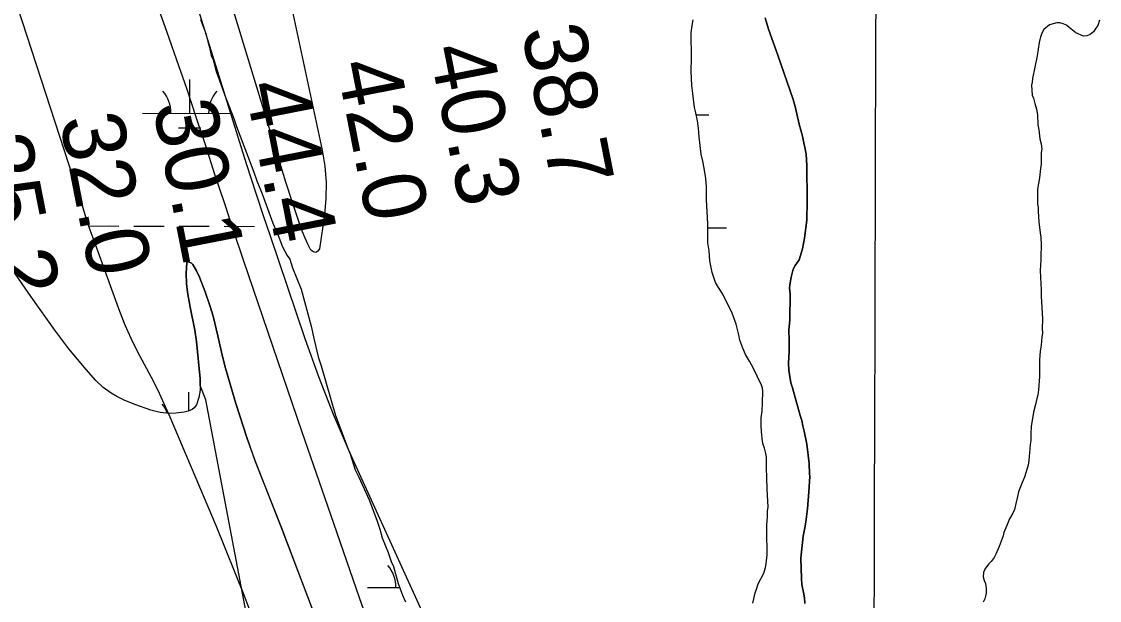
# Model space of a CAD drawing. Extents: x 3161665 to 3199565, y 885729 to 911164.
# Drawn here: x 3180653 to 3181798, y 893161 to 893776 of the extents above; entities that cross this region are included whole.
import ezdxf

# ---------------------------------------------------------------- set-up
doc = ezdxf.new("R2010")
doc.units = 0
for name, color, linetype in [('V-GRID-MAJR', 7, 'Continuous'), ('V-RIVR-RANG', 7, 'Continuous'), ('V-SITE-VEGE', 7, 'Continuous'), ('V-TOPO-MAJR', 7, 'Continuous'), ('V-TOPO-MINR', 7, 'Continuous'), ('V-TOPO-SHOR', 7, 'Continuous'), ('V-WETL-SWMP', 7, 'Continuous')]:
    doc.layers.add(name, color=color, linetype=linetype)

msp = doc.modelspace()

# ---------------------------------------------------------------- linework, layer by layer
at = {"layer": 'V-GRID-MAJR'}
msp.add_spline([(3181553.2, 891152.2), (3181570, 897211.5), (3181586.7, 903274.3), (3181603.5, 909337.1), (3181603.5, 909340.5)], degree=3, dxfattribs=at)
at = {"layer": 'V-SITE-VEGE'}
for p, q in [((3181446.6, 893767.9), (3181443.1, 893779.9)), ((3181745.1, 893772.6), (3181739.1, 893767.8)), ((3181752.9, 893774.6), (3181745.1, 893772.6)), ((3181756.2, 893774.6), (3181752.9, 893774.6)), ((3181759.8, 893773.7), (3181756.2, 893774.6)), ((3181763.4, 893772.1), (3181759.8, 893773.7)), ((3181766.1, 893769.7), (3181763.4, 893772.1)), ((3181769.7, 893767), (3181766.1, 893769.7)), ((3181794.3, 893769.2), (3181791.9, 893765.3)), ((3181796.4, 893771.9), (3181794.3, 893769.2)), ((3181798.3, 893777.6), (3181796.4, 893771.9)), ((3181456.6, 893740.2), (3181446.6, 893767.9)), ((3181735.7, 893759.7), (3181734.2, 893753.8)), ((3181737.3, 893764.5), (3181735.7, 893759.7)), ((3181739.1, 893767.8), (3181737.3, 893764.5)), ((3181773.3, 893764), (3181769.7, 893767)), ((3181781.3, 893760.6), (3181773.3, 893764)), ((3181784.9, 893760.9), (3181781.3, 893760.6)), ((3181788.5, 893762.3), (3181784.9, 893760.9)), ((3181791.9, 893765.3), (3181788.5, 893762.3)), ((3181734.2, 893753.8), (3181732, 893739.7)), ((3181472.7, 893693.3), (3181456.6, 893740.2)), ((3181732, 893739.7), (3181727, 893715.7)), ((3181727, 893715.7), (3181726.7, 893711.8)), ((3181726.7, 893711.8), (3181726, 893708.5)), ((3181726, 893708.5), (3181726.9, 893697.7)), ((3181474.8, 893685.8), (3181472.7, 893693.3)), ((3181726.9, 893697.7), (3181728, 893694.7)), ((3181728, 893694.7), (3181729.5, 893689)), ((3181729.5, 893689), (3181731.5, 893683)), ((3181479.1, 893666.9), (3181474.8, 893685.8)), ((3181731.5, 893683), (3181732.4, 893677)), ((3181482.6, 893654.2), (3181479.1, 893666.9)), ((3181732.4, 893677), (3181732.9, 893666.2)), ((3181732.9, 893666.2), (3181733.8, 893661.1)), ((3181733.8, 893661.1), (3181734.9, 893651.4)), ((3181486.4, 893635), (3181482.6, 893654.2)), ((3181734.9, 893651.4), (3181736.4, 893646)), ((3181736.4, 893646), (3181736.9, 893640.3)), ((3181487.2, 893623), (3181486.4, 893635)), ((3181736.3, 893636.7), (3181736.2, 893624.4)), ((3181736.9, 893640.3), (3181736.3, 893636.7)), ((3181487.5, 893585.5), (3181487.2, 893623)), ((3181736.2, 893624.4), (3181735.6, 893619.9)), ((3181734.6, 893609.8), (3181732.4, 893597.8)), ((3181735.6, 893619.9), (3181734.6, 893609.8)), ((3181732.4, 893597.8), (3181732.3, 893581.9)), ((3181487.4, 893565.1), (3181487.5, 893585.5)), ((3181732.3, 893581.9), (3181733.2, 893578.3)), ((3181733.2, 893578.3), (3181733.1, 893574.1)), ((3181484.8, 893545.9), (3181487.4, 893565.1)), ((3181733.1, 893574.1), (3181733.7, 893563.3)), ((3181733.7, 893563.3), (3181735.1, 893551.5)), ((3181735.1, 893551.5), (3181735.9, 893546.7)), ((3181482.6, 893534.5), (3181484.8, 893545.9)), ((3181735.9, 893546.7), (3181736.2, 893538.6)), ((3181479, 893522.9), (3181482.6, 893534.5)), ((3181736.2, 893538.6), (3181735.8, 893526)), ((3180827.4, 893508.1), (3180828.1, 893520)), ((3180828.1, 893520), (3180828.8, 893520.8)), ((3180828.8, 893520.8), (3180830.1, 893520.8)), ((3180830.1, 893520.8), (3180833.3, 893519.2)), ((3180833.3, 893519.2), (3180834.8, 893517.7)), ((3180834.8, 893517.7), (3180838.7, 893511.1)), ((3181474.7, 893516.9), (3181477.4, 893520.2)), ((3181477.4, 893520.2), (3181479, 893522.9)), ((3181736.1, 893522.7), (3181735.4, 893511.3)), ((3181735.8, 893526), (3181736.1, 893522.7)), ((3180827.9, 893497.7), (3180827.4, 893508.1)), ((3180838.7, 893511.1), (3180841.9, 893504.2)), ((3181470.7, 893504.3), (3181472.6, 893512.7)), ((3181472.6, 893512.7), (3181474.7, 893516.9)), ((3181735.4, 893511.3), (3181735.9, 893497.2)), ((3180829, 893488.5), (3180827.9, 893497.7)), ((3180841.9, 893504.2), (3180847.7, 893488.7)), ((3181468.8, 893492.6), (3181469.2, 893496.2)), ((3181469.2, 893496.2), (3181470.7, 893504.3)), ((3181735.9, 893497.2), (3181736.4, 893490.9)), ((3180831.9, 893472.4), (3180829, 893488.5)), ((3180847.7, 893488.7), (3180853.1, 893473.3)), ((3181469.4, 893486.3), (3181468.8, 893492.6)), ((3181469.2, 893459), (3181469.4, 893486.3)), ((3181736.4, 893490.9), (3181736.4, 893484)), ((3181736.4, 893484), (3181737.7, 893459.7)), ((3180836.8, 893448.1), (3180831.9, 893472.4)), ((3180853.1, 893473.3), (3180856.2, 893462.8)), ((3180856.2, 893462.8), (3180861.2, 893442.1)), ((3181468.2, 893447.9), (3181469.2, 893459)), ((3181737.7, 893459.7), (3181737.3, 893449.8)), ((3181737.3, 893449.8), (3181737.6, 893445.3)), ((3180838.7, 893436), (3180836.8, 893448.1)), ((3180861.2, 893442.1), (3180865.9, 893421.4)), ((3181468.4, 893437.4), (3181468.2, 893447.9)), ((3181468.3, 893425.7), (3181468.4, 893437.4)), ((3181736.9, 893440.5), (3181736.3, 893432.1)), ((3181737.6, 893445.3), (3181736.9, 893440.5)), ((3180842.4, 893396.2), (3180838.7, 893436)), ((3181467.9, 893412.5), (3181468.3, 893425.7)), ((3181735.3, 893425.5), (3181734.7, 893416.6)), ((3181736.3, 893432.1), (3181735.3, 893425.5)), ((3180865.9, 893421.4), (3180869.5, 893407.7)), ((3181734.7, 893416.6), (3181734.5, 893398.6)), ((3180869.5, 893407.7), (3180880.4, 893370.1)), ((3181468.2, 893405.6), (3181467.9, 893412.5)), ((3181468.7, 893400.8), (3181468.2, 893405.6)), ((3180842.6, 893389.3), (3180842.4, 893396.2)), ((3181470.2, 893392.1), (3181468.7, 893400.8)), ((3181471.9, 893386.7), (3181470.2, 893392.1)), ((3181734.5, 893398.6), (3181733.5, 893384.5)), ((3180848.3, 893374.1), (3180842.6, 893389.3)), ((3181480.1, 893357.3), (3181471.9, 893386.7)), ((3181733.5, 893384.5), (3181732.6, 893378.8)), ((3180898.3, 893112.3), (3180848.3, 893374.1)), ((3180880.4, 893370.1), (3180892.3, 893332.8)), ((3181730.4, 893368.9), (3181728.2, 893360.8)), ((3181731.6, 893375.2), (3181730.4, 893368.9)), ((3181732.6, 893378.8), (3181731.6, 893375.2)), ((3181481.9, 893352.1), (3181480.1, 893357.3)), ((3181728.2, 893360.8), (3181725.7, 893345.5)), ((3181483, 893346.4), (3181481.9, 893352.1)), ((3181484.5, 893340.7), (3181483, 893346.4)), ((3181725.7, 893345.5), (3181725.4, 893337.7)), ((3181487.4, 893326.9), (3181484.5, 893340.7)), ((3181725.4, 893337.7), (3181725.3, 893330.8)), ((3180892.3, 893332.8), (3180901, 893308.3)), ((3181489.6, 893306.2), (3181487.4, 893326.9)), ((3181724.7, 893326.6), (3181723.1, 893309.5)), ((3181725.3, 893330.8), (3181724.7, 893326.6)), ((3180901, 893308.3), (3180928.8, 893237.8)), ((3181490.2, 893295.4), (3181489.6, 893306.2)), ((3181722.4, 893304.4), (3181718.7, 893291.6)), ((3181723.1, 893309.5), (3181722.4, 893304.4)), ((3181489.4, 893276.2), (3181490.4, 893292.4)), ((3181490.4, 893292.4), (3181490.2, 893295.4)), ((3181718.7, 893291.6), (3181716, 893285.9)), ((3181714.4, 893281.4), (3181712.3, 893276)), ((3181716, 893285.9), (3181714.4, 893281.4)), ((3181487.8, 893257.9), (3181489.4, 893276.2)), ((3181709.8, 893265.2), (3181708, 893257.5)), ((3181711.1, 893271.2), (3181709.8, 893265.2)), ((3181712.3, 893276), (3181711.1, 893271.2)), ((3181486.5, 893246.8), (3181487.8, 893257.9)), ((3181708, 893257.5), (3181706.1, 893253.3)), ((3181485.5, 893239.6), (3181486.5, 893246.8)), ((3181702.8, 893247.3), (3181700, 893240.4)), ((3181706.1, 893253.3), (3181702.8, 893247.3)), ((3180928.8, 893237.8), (3180972.7, 893122.6)), ((3181483.4, 893229.1), (3181485.5, 893239.6)), ((3181696.7, 893232.9), (3181695.8, 893229.3)), ((3181700, 893240.4), (3181696.7, 893232.9)), ((3181480.8, 893205.5), (3181483.4, 893229.1)), ((3181695.8, 893229.3), (3181691.5, 893218)), ((3181688.1, 893209.9), (3181686.3, 893206.3)), ((3181691.5, 893218), (3181688.1, 893209.9)), ((3181481.5, 893184.1), (3181480.8, 893205.5)), ((3181680.5, 893199.2), (3181676.6, 893193.8)), ((3181683.3, 893202.1), (3181680.5, 893199.2)), ((3181686.3, 893206.3), (3181683.3, 893202.1)), ((3181675.1, 893190.2), (3181674.7, 893185.7)), ((3181674.7, 893185.7), (3181675.6, 893181.8)), ((3181676.6, 893193.8), (3181675.1, 893190.2)), ((3181482.1, 893177.5), (3181481.5, 893184.1)), ((3181484.1, 893167.3), (3181482.1, 893177.5)), ((3181675.6, 893181.8), (3181677.1, 893178.8)), ((3181677.1, 893178.8), (3181677.9, 893173.7)), ((3181677.9, 893173.7), (3181677.9, 893168.3)), ((3181484.7, 893163.4), (3181484.1, 893167.3)), ((3181485.2, 893157.4), (3181484.7, 893163.4)), ((3181676.4, 893162.3), (3181674.5, 893158.7)), ((3181677.3, 893165.3), (3181676.4, 893162.3)), ((3181677.9, 893168.3), (3181677.3, 893165.3))]:
    msp.add_line(p, q, dxfattribs=at)
at = {"layer": 'V-TOPO-MAJR'}
msp.add_lwpolyline([(3181343.1, 892486.4), (3181319.1, 892555.9), (3181294.9, 892625.4), (3181270.7, 892694.8), (3181241.9, 892777.2), (3181232, 892805.4), (3181221.9, 892833.5), (3181001.3, 893318.7), (3180984.3, 893358.2), (3180968.7, 893398.2), (3180954.2, 893438.7), (3180916.7, 893549), (3180909.8, 893569.5), (3180903, 893590.1), (3180896.3, 893610.7), (3180889.7, 893631.4), (3180849, 893761.2), (3180822.7, 893847)], dxfattribs=at)
at = {"layer": 'V-TOPO-MINR'}
for points in [[(3180889.3, 894026.8), (3180972.2, 893639.4), (3180974.9, 893622.3), (3180976.4, 893605.1), (3180976.1, 893588), (3180974.5, 893570.7), (3180969.3, 893534.6), (3180967.4, 893531.9), (3180965.4, 893530.6), (3180962.9, 893531.1), (3180960.2, 893533), (3180956.9, 893539.4), (3180953.9, 893545.9), (3180951.1, 893552.6), (3180948.7, 893559.4), (3180939.1, 893587.8), (3180937.6, 893592.3), (3180936.2, 893596.7), (3180934.8, 893601.1), (3180933.4, 893605.5), (3180780.7, 894106.2)], [(3181395.1, 892231.3), (3181147.5, 892778.3), (3181135.9, 892811.7), (3181124.1, 892845.2), (3181112.3, 892878.6), (3181073.7, 892987.5), (3181042.6, 893075.5), (3181011.8, 893163.5), (3180981.3, 893251.6), (3180951, 893339.7), (3180888.6, 893522.5), (3180878.3, 893552.8), (3180868.2, 893583.2), (3180858.2, 893613.6), (3180848.3, 893644.1), (3180838.3, 893674.5), (3180828.2, 893704.9), (3180817.7, 893735.2), (3180807.1, 893765.4), (3180759.8, 893897.1)], [(3180623.3, 893867.9), (3180717.6, 893578), (3180721.4, 893566.4), (3180725.3, 893554.8), (3180729.4, 893543.3), (3180733.5, 893531.8), (3180756.8, 893468.3), (3180762.5, 893453.8), (3180768.6, 893439.5), (3180775.5, 893425.6), (3180782.8, 893411.8), (3180790.2, 893398.1), (3180797.3, 893384.2), (3180803.9, 893370.1), (3180810.3, 893355.9), (3180859.5, 893239.6), (3180888.9, 893166.5), (3180916.4, 893092.9)]]:
    msp.add_lwpolyline(points, dxfattribs=at)
at = {"layer": 'V-TOPO-SHOR'}
for points in [[(3181443.1, 893779.9), (3181446.6, 893767.9), (3181456.6, 893740.2), (3181472.7, 893693.3), (3181474.8, 893685.8), (3181479.1, 893666.9), (3181482.6, 893654.2), (3181486.4, 893635), (3181487.2, 893623), (3181487.5, 893585.5), (3181487.4, 893565.1), (3181484.8, 893545.9), (3181482.6, 893534.5), (3181479, 893522.9), (3181477.4, 893520.2), (3181474.7, 893516.9), (3181472.6, 893512.7), (3181470.7, 893504.3), (3181469.2, 893496.2), (3181468.8, 893492.6), (3181469.4, 893486.3), (3181469.2, 893459), (3181468.2, 893447.9), (3181468.4, 893437.4), (3181468.3, 893425.7), (3181467.9, 893412.5), (3181468.2, 893405.6), (3181468.7, 893400.8), (3181470.2, 893392.1), (3181471.9, 893386.7), (3181480.1, 893357.3), (3181481.9, 893352.1), (3181483, 893346.4), (3181484.5, 893340.7), (3181487.4, 893326.9), (3181489.6, 893306.2), (3181490.2, 893295.4), (3181490.4, 893292.4), (3181489.4, 893276.2), (3181487.8, 893257.9), (3181486.5, 893246.8), (3181485.5, 893239.6), (3181483.4, 893229.1), (3181480.8, 893205.5), (3181481.5, 893184.1), (3181482.1, 893177.5), (3181484.1, 893167.3), (3181484.7, 893163.4), (3181485.2, 893157.4)], [(3181798.3, 893777.6), (3181796.4, 893771.9), (3181794.3, 893769.2), (3181791.9, 893765.3), (3181788.5, 893762.3), (3181784.9, 893760.9), (3181781.3, 893760.6), (3181773.3, 893764), (3181769.7, 893767), (3181766.1, 893769.7), (3181763.4, 893772.1), (3181759.8, 893773.7), (3181756.2, 893774.6), (3181752.9, 893774.6), (3181745.1, 893772.6), (3181739.1, 893767.8), (3181737.3, 893764.5), (3181735.7, 893759.7), (3181734.2, 893753.8), (3181732, 893739.7), (3181727, 893715.7), (3181726.7, 893711.8), (3181726, 893708.5), (3181726.9, 893697.7), (3181728, 893694.7), (3181729.5, 893689), (3181731.5, 893683), (3181732.4, 893677), (3181732.9, 893666.2), (3181733.8, 893661.1), (3181734.9, 893651.4), (3181736.4, 893646), (3181736.9, 893640.3), (3181736.3, 893636.7), (3181736.2, 893624.4), (3181735.6, 893619.9), (3181734.6, 893609.8), (3181732.4, 893597.8), (3181732.3, 893581.9), (3181733.2, 893578.3), (3181733.1, 893574.1), (3181733.7, 893563.3), (3181735.1, 893551.5), (3181735.9, 893546.7), (3181736.2, 893538.6), (3181735.8, 893526), (3181736.1, 893522.7), (3181735.4, 893511.3), (3181735.9, 893497.2), (3181736.4, 893490.9), (3181736.4, 893484), (3181737.7, 893459.7), (3181737.3, 893449.8), (3181737.6, 893445.3), (3181736.9, 893440.5), (3181736.3, 893432.1), (3181735.3, 893425.5), (3181734.7, 893416.6), (3181734.5, 893398.6), (3181733.5, 893384.5), (3181732.6, 893378.8), (3181731.6, 893375.2), (3181730.4, 893368.9), (3181728.2, 893360.8)], [(3181728.2, 893360.8), (3181725.7, 893345.5), (3181725.4, 893337.7), (3181725.3, 893330.8), (3181724.7, 893326.6), (3181723.1, 893309.5), (3181722.4, 893304.4), (3181718.7, 893291.6), (3181716, 893285.9), (3181714.4, 893281.4), (3181712.3, 893276), (3181711.1, 893271.2), (3181709.8, 893265.2), (3181708, 893257.5), (3181706.1, 893253.3), (3181702.8, 893247.3), (3181700, 893240.4), (3181696.7, 893232.9), (3181695.8, 893229.3), (3181691.5, 893218), (3181688.1, 893209.9), (3181686.3, 893206.3), (3181683.3, 893202.1), (3181680.5, 893199.2), (3181676.6, 893193.8), (3181675.1, 893190.2), (3181674.7, 893185.7), (3181675.6, 893181.8), (3181677.1, 893178.8), (3181677.9, 893173.7), (3181677.9, 893168.3), (3181677.3, 893165.3), (3181676.4, 893162.3), (3181674.5, 893158.7)]]:
    msp.add_lwpolyline(points, dxfattribs=at)
at = {"layer": 'V-WETL-SWMP'}
for p, q in [((3180831.3, 893678.5), (3180831.4, 893714.5)), ((3180781.3, 893678.7), (3180876.3, 893678.4)), ((3181369.5, 893677), (3181383.2, 893677)), ((3180819.3, 893663.1), (3180843.3, 893663.1)), ((3180724.1, 893558.8), (3180756.1, 893558.7)), ((3180772.1, 893558.6), (3180804.1, 893558.5)), ((3180820.1, 893558.5), (3180852.1, 893558.4)), ((3180868.1, 893558.4), (3180900.1, 893558.3)), ((3181382, 893556.9), (3181402, 893556.9)), ((3180830.4, 893362.3), (3180830.5, 893381.9)), ((3181020.4, 893174.5), (3181054.4, 893174.4))]:
    msp.add_line(p, q, dxfattribs=at)
for points in [[(3180842.9, 893778.3), (3180848.6, 893763.3), (3180850.5, 893754.9), (3180852.4, 893748.4), (3180854.3, 893740), (3180856.2, 893735.4), (3180859.4, 893723.1), (3180861.3, 893718.5), (3180868.2, 893698.4), (3180878.4, 893673), (3180880.9, 893664.6), (3180899.4, 893615.8), (3180902.6, 893606.7), (3180908.3, 893593.1), (3180919.7, 893561.9), (3180924.2, 893551.5), (3180929.9, 893536.5), (3180935, 893527.4), (3180937.6, 893523.5), (3180940.7, 893514.4), (3180949.7, 893491.7), (3180960.4, 893452.1), (3180963.5, 893437.8), (3180967.9, 893419.6), (3180971.1, 893409.9), (3180986.2, 893357.2), (3180999.6, 893321.5), (3181001.5, 893317.6)], [(3181430, 893157.8), (3181431, 893162.3), (3181432.5, 893168.6), (3181433.7, 893172.5), (3181435.6, 893178.2), (3181441.4, 893189.8), (3181443.2, 893195.5), (3181444.1, 893199.4), (3181445.1, 893209.3), (3181444.7, 893234.8), (3181444.7, 893240.8), (3181445.4, 893249.8), (3181445.5, 893255.5), (3181446.1, 893260), (3181445.6, 893272.3), (3181445, 893278.9), (3181444.8, 893291.5), (3181444.3, 893301.1), (3181444.4, 893312.8), (3181443.8, 893316.7), (3181442.4, 893322.4), (3181440.9, 893326.4), (3181440.3, 893330), (3181439.2, 893339.9), (3181438.6, 893346.5), (3181438.7, 893354.9), (3181439.7, 893361.8), (3181440.3, 893370.5), (3181440.4, 893383.1), (3181440.1, 893386.4), (3181438.7, 893390.6), (3181436.3, 893395.1), (3181432.8, 893402.9), (3181428.6, 893411.3), (3181426.2, 893415), (3181422.1, 893422.2), (3181419.2, 893428.8), (3181416.2, 893437.5), (3181414.8, 893442.9), (3181412.1, 893454.4), (3181408, 893466.1), (3181401.2, 893479.9), (3181397.1, 893487.5), (3181393.5, 893493.5), (3181390.3, 893498.6), (3181386.8, 893509.2), (3181384.1, 893521.8), (3181383.3, 893532.3), (3181381.9, 893541), (3181382, 893561.1), (3181380.7, 893586.9), (3181380.5, 893600.4), (3181380, 893609.1), (3181378.3, 893620.2), (3181376.8, 893627.7), (3181375.1, 893635.2), (3181372.8, 893653.6), (3181372, 893662.6), (3181370.9, 893670.7), (3181369.1, 893679.1), (3181367.7, 893684.8), (3181366, 893699.5), (3181365.1, 893708.2), (3181364.4, 893722.9), (3181364.5, 893737), (3181364.4, 893764), (3181365.3, 893771.8), (3181366.3, 893777.8)], [(3181443.1, 893779.9), (3181446.6, 893767.9), (3181456.6, 893740.2), (3181472.7, 893693.3), (3181474.8, 893685.8), (3181479.1, 893666.9), (3181482.6, 893654.2), (3181486.4, 893635), (3181487.2, 893623), (3181487.5, 893585.5), (3181487.4, 893565.1), (3181484.8, 893545.9), (3181482.6, 893534.5), (3181479, 893522.9), (3181477.4, 893520.2), (3181474.7, 893516.9), (3181472.6, 893512.7), (3181470.7, 893504.3), (3181469.2, 893496.2), (3181468.8, 893492.6), (3181469.4, 893486.3), (3181469.2, 893459), (3181468.2, 893447.9), (3181468.4, 893437.4), (3181468.3, 893425.7), (3181467.9, 893412.5), (3181468.2, 893405.6), (3181468.7, 893400.8), (3181470.2, 893392.1), (3181471.9, 893386.7), (3181480.1, 893357.3), (3181481.9, 893352.1), (3181483, 893346.4), (3181484.5, 893340.7), (3181487.4, 893326.9), (3181489.6, 893306.2), (3181490.2, 893295.4), (3181490.4, 893292.4), (3181489.4, 893276.2), (3181487.8, 893257.9), (3181486.5, 893246.8), (3181485.5, 893239.6), (3181483.4, 893229.1), (3181480.8, 893205.5), (3181481.5, 893184.1), (3181482.1, 893177.5), (3181484.1, 893167.3), (3181484.7, 893163.4), (3181485.2, 893157.4)], [(3180865.9, 893421.4), (3180861.2, 893442.1), (3180856.2, 893462.8), (3180853.1, 893473.2), (3180847.7, 893488.7), (3180841.9, 893504.2), (3180838.7, 893511.1), (3180834.8, 893517.7), (3180833.3, 893519.2), (3180830.1, 893520.8), (3180828.8, 893520.8), (3180828.1, 893520), (3180827.4, 893508.1), (3180827.9, 893497.7), (3180829, 893488.5), (3180831.9, 893472.4), (3180836.8, 893448.1), (3180838.7, 893436), (3180842.4, 893396.2), (3180842.6, 893389.3), (3180842.4, 893384.1), (3180841.1, 893376.4), (3180838.4, 893368.7), (3180836.2, 893365.5), (3180833.9, 893363.8), (3180829.8, 893362), (3180825.6, 893360.9), (3180816.7, 893359.6), (3180809.9, 893359.5), (3180799.8, 893360.5), (3180789.9, 893363), (3180774, 893368.5), (3180762.3, 893373.2), (3180753.8, 893377.4), (3180747.8, 893380.9), (3180739.2, 893387), (3180731.4, 893394.4), (3180721.1, 893406), (3180702.8, 893428.2), (3180687.8, 893448.1), (3180662.7, 893483.5), (3180625.8, 893536.3)], [(3181194.7, 892531.5), (3181164.7, 892599.9), (3181134.8, 892668.3), (3181097.2, 892755.5), (3181078.9, 892799.4), (3181061.2, 892843.5), (3181057.7, 892853.8), (3181055.5, 892863.2), (3181052.7, 892879.8), (3181049.2, 892905), (3181046.7, 892917.4), (3181043.2, 892929.5), (3181015.4, 893006.9), (3180972.7, 893122.6), (3180928.8, 893237.8), (3180901.1, 893308.3), (3180892.3, 893332.8), (3180880.4, 893370.1), (3180869.5, 893407.7), (3180865.9, 893421.4)], [(3181001.5, 893317.6), (3181007.2, 893299.4), (3181011, 893291.6), (3181021.9, 893267.5), (3181030.1, 893246.1), (3181033.3, 893236.3), (3181035.8, 893227.3), (3181042.2, 893211.7), (3181045.3, 893201.9), (3181047.9, 893196.7), (3181052.9, 893178.5), (3181057.4, 893166.2), (3181060.6, 893159)]]:
    msp.add_lwpolyline(points, dxfattribs=at)
for centre, start, end in [((3180776.1, 893679.2), 359.0698, 40.6135), ((3180886.6, 893678.9), 139.0698, 180.6135), ((3180775.2, 893346.5), 21.9591, 40.6135), ((3181015.2, 893175), 359.0698, 40.6135)]:
    msp.add_arc(centre, 35.2, start, end, dxfattribs=at)

# ---------------------------------------------------------------- texts
at = {"layer": 'V-RIVR-RANG'}
for s, p in [('38.7', (3181183.8, 893766.9)), ('40.3', (3181085.7, 893747.4)), ('42.0', (3180987.1, 893730.8)), ('44.4', (3180889.6, 893708.5)), ('30.1', (3180791.9, 893686.7)), ('32.0', (3180692.8, 893672.4)), ('35.2', (3180595.3, 893650.1))]:
    msp.add_text(s, height=67, rotation=281.0883, dxfattribs=at).set_placement(p)

doc.saveas('drawing.dxf')
